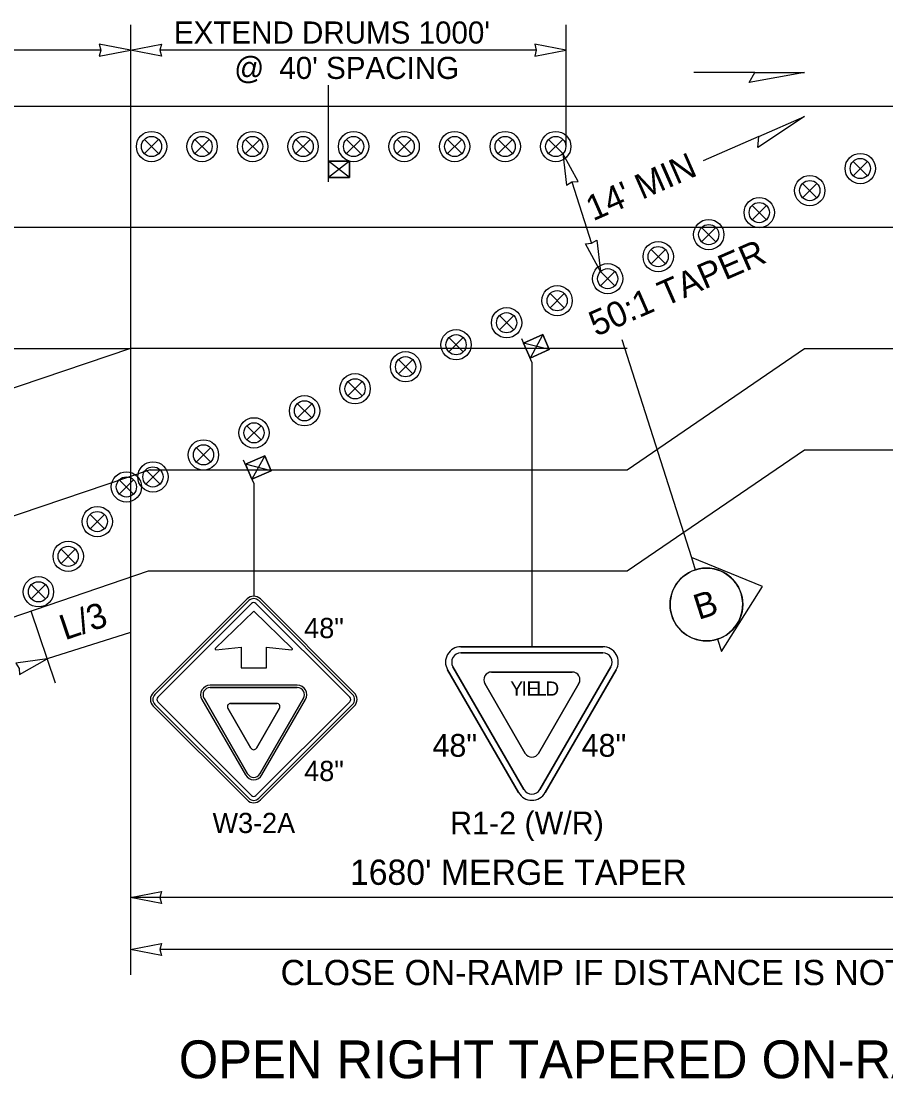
# Model space of a CAD drawing. Extents: x 99999 to 100116, y 99995 to 100013.
# Drawn here: x 100070.257 to 100072.995, y 100004.799 to 100008.148 of the extents above; entities that cross this region are included whole.
import ezdxf

# ---------------------------------------------------------------- set-up
doc = ezdxf.new("R2010")
doc.units = 0
for name, color, linetype in [('RD_MK_LineEdgeYellow', 7, 'Continuous'), ('RD_MK_LineLane', 7, 'Continuous'), ('SH_DE_DetailHeading2Text', 7, 'Continuous'), ('SH_GI_SectionCut', 7, 'Continuous'), ('TR_SN_ConstructionSigns', 7, 'Continuous'), ('TR_WZ_PortableSignMount5ftMinBlk-Org', 7, 'Continuous'), ('TR_WZ_PortableSignMount5ftMinRed-Wht', 7, 'Continuous'), ('TR_WZ_TrafficSafetyDrum', 7, 'Continuous'), ('TR_WZ_WorkZoneDetails', 7, 'Continuous'), ('TR_WZ_WorkZoneTextCurrent', 7, 'Continuous')]:
    doc.layers.add(name, color=color, linetype=linetype)

msp = doc.modelspace()

# ---------------------------------------------------------------- linework, layer by layer
at = {"layer": 'RD_MK_LineEdgeYellow'}
for p, q in [((100068.195, 100007.8789), (100075.43, 100007.8789)), ((100072.1758, 100006.7269), (100072.7368, 100007.1109)), ((100072.7368, 100007.1109), (100075.43, 100007.1109)), ((100070.6655, 100006.7269), (100068.195, 100005.8927)), ((100070.6655, 100006.7269), (100072.1758, 100006.7269))]:
    msp.add_line(p, q, dxfattribs=at)
at = {"layer": 'RD_MK_LineLane'}
for points in [[(100075.43, 100007.4949), (100068.195, 100007.4949)], [(100072.1758, 100007.1109), (100070.6024, 100007.1109)], [(100072.1758, 100007.1109), (100070.6024, 100007.1109)]]:
    msp.add_lwpolyline(points, dxfattribs=at)
at = {"layer": 'SH_GI_SectionCut'}
for p, q in [((100072.1583, 100007.1399), (100072.3791, 100006.4491)), ((100072.3791, 100006.4491), (100072.3915, 100006.4103)), ((100072.6038, 100006.3572), (100072.3791, 100006.4491)), ((100072.474, 100006.1521), (100072.6038, 100006.3572)), ((100072.4616, 100006.1909), (100072.474, 100006.1521))]:
    msp.add_line(p, q, dxfattribs=at)
msp.add_circle((100072.4266, 100006.3006), 0.1152, dxfattribs=at)
for start, end in [(17.7228, 287.7205), (287.7205, 107.725), (287.7205, 17.7228)]:
    msp.add_arc((100072.4266, 100006.3006), 0.1152, start, end, dxfattribs=at)
at = {"layer": 'TR_SN_ConstructionSigns'}
for p, q in [((100070.9719, 100006.3181), (100070.6749, 100006.0211)), ((100071.3113, 100006.0211), (100071.0143, 100006.3181)), ((100070.9772, 100006.3128), (100070.6802, 100006.0158)), ((100070.689, 100006.007), (100070.986, 100006.304)), ((100071.0002, 100006.304), (100071.2971, 100006.007)), ((100071.306, 100006.0158), (100071.009, 100006.3128)), ((100070.9931, 100006.2799), (100070.8713, 100006.1617)), ((100071.1148, 100006.1617), (100070.9931, 100006.2799)), ((100070.8733, 100006.1574), (100070.9531, 100006.1658)), ((100070.9531, 100006.1658), (100070.9531, 100006.0999)), ((100071.0331, 100006.0999), (100071.0331, 100006.1658)), ((100071.0331, 100006.1658), (100071.1128, 100006.1574)), ((100072.0987, 100006.1669), (100071.6491, 100006.1669)), ((100071.6491, 100006.1475), (100071.6491, 100006.1476)), ((100071.6491, 100006.1476), (100071.8739, 100006.1476)), ((100071.8739, 100006.1476), (100071.6491, 100006.1476)), ((100071.6491, 100006.1476), (100071.6491, 100006.1475)), ((100070.9531, 100006.0999), (100071.0331, 100006.0999)), ((100071.8317, 100005.7052), (100071.6069, 100006.0939)), ((100071.6069, 100006.0939), (100071.8317, 100005.7052)), ((100071.8486, 100005.715), (100071.6238, 100006.1036)), ((100071.6238, 100006.1036), (100071.8486, 100005.715)), ((100071.8739, 100006.0867), (100071.7461, 100006.0867)), ((100071.7461, 100006.0867), (100071.8739, 100006.0867)), ((100072.0017, 100006.0867), (100071.8739, 100006.0867)), ((100071.8739, 100006.0867), (100072.0017, 100006.0867)), ((100072.124, 100006.1036), (100071.8992, 100005.715)), ((100071.8992, 100005.715), (100072.124, 100006.1036)), ((100072.1408, 100006.0939), (100071.916, 100005.7052)), ((100071.916, 100005.7052), (100072.1408, 100006.0939)), ((100071.725, 100006.0502), (100071.8528, 100005.8293)), ((100071.8528, 100005.8293), (100071.725, 100006.0502)), ((100071.895, 100005.8293), (100072.0228, 100006.0502)), ((100072.0228, 100006.0502), (100071.895, 100005.8293)), ((100071.1311, 100006.0449), (100070.855, 100006.0449)), ((100070.855, 100006.0374), (100071.1311, 100006.0374)), ((100071.1311, 100006.0374), (100070.855, 100006.0374)), ((100070.6802, 100005.984), (100070.9772, 100005.687)), ((100070.986, 100005.6959), (100070.689, 100005.9929)), ((100070.8291, 100005.9999), (100070.9671, 100005.7608)), ((100070.9736, 100005.7646), (100070.8356, 100006.0037)), ((100070.8356, 100006.0037), (100070.9736, 100005.7646)), ((100071.0662, 100005.9874), (100070.92, 100005.9874)), ((100070.92, 100005.9874), (100071.0662, 100005.9874)), ((100071.2971, 100005.9929), (100071.0002, 100005.6959)), ((100071.009, 100005.687), (100071.306, 100005.984)), ((100071.1506, 100006.0037), (100071.0126, 100005.7646)), ((100071.0126, 100005.7646), (100071.1506, 100006.0037)), ((100071.0191, 100005.7608), (100071.1571, 100005.9999)), ((100070.6749, 100005.9787), (100070.9719, 100005.6817)), ((100070.9113, 100005.9724), (100070.9844, 100005.8458)), ((100070.9844, 100005.8458), (100070.9113, 100005.9724)), ((100071.0017, 100005.8458), (100071.0748, 100005.9724)), ((100071.0748, 100005.9724), (100071.0017, 100005.8458)), ((100071.0143, 100005.6817), (100071.3113, 100005.9787))]:
    msp.add_line(p, q, dxfattribs=at)
for points in [[(100071.6491, 100006.1669), (100072.0987, 100006.1669)], [(100071.8739, 100006.1476), (100072.0987, 100006.1476), (100072.0987, 100006.1475)], [(100072.0987, 100006.1475), (100072.0987, 100006.1476), (100071.8739, 100006.1476)]]:
    msp.add_lwpolyline(points, dxfattribs=at)
for centre, radius, start, end in [((100070.9931, 100006.2969), 0.03, 45, 135), ((100070.9931, 100006.2969), 0.0225, 45, 135), ((100070.9931, 100006.2969), 0.01, 45, 135), ((100070.8731, 100006.1599), 0.0025, 134.1559, 275.9533), ((100071.1131, 100006.1599), 0.0025, 264.0467, 45.8441), ((100071.6491, 100006.1182), 0.0487, 90, 210.0517), ((100071.6491, 100006.1182), 0.0487, 90, 210.0517), ((100072.0987, 100006.1182), 0.0487, 329.9522, 90), ((100072.0987, 100006.1182), 0.0487, 329.9522, 90), ((100071.6491, 100006.1182), 0.0292, 90, 210.0517), ((100071.6491, 100006.1182), 0.0292, 90, 210.0517), ((100072.0987, 100006.1182), 0.0292, 329.9522, 90), ((100072.0987, 100006.1182), 0.0292, 329.9522, 90), ((100071.7461, 100006.0624), 0.0244, 90, 210.0513), ((100071.7461, 100006.0624), 0.0244, 90, 210.0513), ((100072.0017, 100006.0624), 0.0244, 329.9514, 90), ((100072.0017, 100006.0624), 0.0244, 329.9514, 90), ((100070.6961, 100005.9999), 0.03, 135, 225), ((100070.6961, 100005.9999), 0.0225, 135, 225), ((100070.855, 100006.0149), 0.03, 90, 210), ((100070.855, 100006.0149), 0.0225, 90, 210), ((100070.855, 100006.0149), 0.0225, 90, 210), ((100071.1311, 100006.0149), 0.03, 330, 90), ((100071.1311, 100006.0149), 0.0225, 330, 90), ((100071.1311, 100006.0149), 0.0225, 330, 90), ((100071.2901, 100005.9999), 0.0225, 315, 45), ((100071.2901, 100005.9999), 0.03, 315, 45), ((100070.6961, 100005.9999), 0.01, 135, 225), ((100070.92, 100005.9774), 0.01, 90, 210), ((100070.92, 100005.9774), 0.01, 90, 210), ((100071.0662, 100005.9774), 0.01, 330, 90), ((100071.0662, 100005.9774), 0.01, 330, 90), ((100071.2901, 100005.9999), 0.01, 315, 45), ((100070.9931, 100005.8508), 0.01, 210, 330), ((100070.9931, 100005.8508), 0.01, 210, 330), ((100071.8739, 100005.8415), 0.0244, 210.0519, 329.9525), ((100071.8739, 100005.8415), 0.0244, 210.0519, 329.9525), ((100070.9931, 100005.7758), 0.03, 210, 330), ((100070.9931, 100005.7758), 0.0225, 210, 330), ((100070.9931, 100005.7758), 0.0225, 210, 330), ((100071.8739, 100005.7296), 0.0292, 210.0518, 329.9516), ((100071.8739, 100005.7296), 0.0292, 210.0518, 329.9516), ((100070.9931, 100005.7029), 0.03, 225, 315), ((100070.9931, 100005.7029), 0.0225, 225, 315), ((100070.9931, 100005.7029), 0.01, 225, 315), ((100071.8739, 100005.7296), 0.0487, 210.0518, 329.9516), ((100071.8739, 100005.7296), 0.0487, 210.0518, 329.9516)]:
    msp.add_arc(centre, radius, start, end, dxfattribs=at)
at = {"layer": 'TR_WZ_PortableSignMount5ftMinBlk-Org'}
for p, q in [((100071.2294, 100007.6389), (100071.2294, 100007.7189)), ((100071.2961, 100007.7049), (100071.2294, 100007.6529)), ((100071.2961, 100007.6529), (100071.2294, 100007.7049)), ((100071.2627, 100007.6789), (100071.2627, 100007.6789)), ((100071.2628, 100007.679), (100071.2628, 100007.679)), ((100070.9931, 100006.6844), (100070.9611, 100006.7577)), ((100071.0279, 100006.7715), (100070.9875, 100006.6972)), ((100071.0486, 100006.7239), (100070.9667, 100006.7449)), ((100071.0077, 100006.7344), (100071.0077, 100006.7344)), ((100071.0078, 100006.7345), (100071.0078, 100006.7345))]:
    msp.add_line(p, q, dxfattribs=at)
for points in [[(100071.2961, 100007.7049), (100071.2961, 100007.6529), (100071.2294, 100007.6529), (100071.2294, 100007.7049)], [(100071.2294, 100007.6529), (100071.2961, 100007.6529), (100071.2961, 100007.7049), (100071.2294, 100007.7049)], [(100071.0279, 100006.7715), (100071.0486, 100006.7239), (100070.9875, 100006.6972), (100070.9667, 100006.7449)], [(100070.9875, 100006.6972), (100071.0486, 100006.7239), (100071.0279, 100006.7715), (100070.9667, 100006.7449)]]:
    msp.add_lwpolyline(points, close=True, dxfattribs=at)
at = {"layer": 'TR_WZ_PortableSignMount5ftMinRed-Wht'}
for p, q in [((100071.9083, 100007.1554), (100071.868, 100007.0811)), ((100071.8736, 100007.0683), (100071.8416, 100007.1416)), ((100071.9291, 100007.1078), (100071.8472, 100007.1287)), ((100071.8881, 100007.1183), (100071.8881, 100007.1183)), ((100071.8882, 100007.1184), (100071.8882, 100007.1184))]:
    msp.add_line(p, q, dxfattribs=at)
for points in [[(100071.9083, 100007.1554), (100071.9291, 100007.1078), (100071.868, 100007.0811), (100071.8472, 100007.1287)], [(100071.868, 100007.0811), (100071.9291, 100007.1078), (100071.9083, 100007.1554), (100071.8472, 100007.1287)]]:
    msp.add_lwpolyline(points, close=True, dxfattribs=at)
at = {"layer": 'TR_WZ_TrafficSafetyDrum'}
for p, q in [((100070.6468, 100007.7735), (100070.692, 100007.7283)), ((100070.692, 100007.7735), (100070.6468, 100007.7283)), ((100070.8068, 100007.7735), (100070.852, 100007.7283)), ((100070.852, 100007.7735), (100070.8068, 100007.7283)), ((100070.9668, 100007.7735), (100071.012, 100007.7283)), ((100071.012, 100007.7735), (100070.9668, 100007.7283)), ((100071.1268, 100007.7735), (100071.172, 100007.7283)), ((100071.172, 100007.7735), (100071.1268, 100007.7283)), ((100071.2868, 100007.7735), (100071.332, 100007.7283)), ((100071.332, 100007.7735), (100071.2868, 100007.7283)), ((100071.4468, 100007.7735), (100071.492, 100007.7283)), ((100071.492, 100007.7735), (100071.4468, 100007.7283)), ((100071.6068, 100007.7735), (100071.652, 100007.7283)), ((100071.652, 100007.7735), (100071.6068, 100007.7283)), ((100071.7668, 100007.7735), (100071.812, 100007.7283)), ((100071.812, 100007.7735), (100071.7668, 100007.7283)), ((100071.9268, 100007.7735), (100071.972, 100007.7283)), ((100071.972, 100007.7735), (100071.9268, 100007.7283)), ((100072.8913, 100007.7038), (100072.9366, 100007.6585)), ((100072.9366, 100007.7038), (100072.8913, 100007.6585)), ((100072.7313, 100007.634), (100072.7766, 100007.5888)), ((100072.7766, 100007.634), (100072.7313, 100007.5888)), ((100072.5713, 100007.5643), (100072.6166, 100007.519)), ((100072.6166, 100007.5643), (100072.5713, 100007.519)), ((100072.4113, 100007.4946), (100072.4566, 100007.4493)), ((100072.4566, 100007.4946), (100072.4113, 100007.4493)), ((100072.2513, 100007.4248), (100072.2966, 100007.3796)), ((100072.2966, 100007.4248), (100072.2513, 100007.3796)), ((100072.0913, 100007.3551), (100072.1366, 100007.3098)), ((100072.1366, 100007.3551), (100072.0913, 100007.3098)), ((100071.9313, 100007.2853), (100071.9766, 100007.2401)), ((100071.9766, 100007.2853), (100071.9313, 100007.2401)), ((100071.7713, 100007.2156), (100071.8166, 100007.1703)), ((100071.8166, 100007.2156), (100071.7713, 100007.1703)), ((100071.6113, 100007.1458), (100071.6566, 100007.1006)), ((100071.6566, 100007.1458), (100071.6113, 100007.1006)), ((100071.4513, 100007.0761), (100071.4966, 100007.0308)), ((100071.4966, 100007.0761), (100071.4513, 100007.0308)), ((100071.2913, 100007.0063), (100071.3366, 100006.9611)), ((100071.3366, 100007.0063), (100071.2913, 100006.9611)), ((100071.1313, 100006.9366), (100071.1766, 100006.8913)), ((100071.1766, 100006.9366), (100071.1313, 100006.8913)), ((100070.9713, 100006.8669), (100071.0166, 100006.8216)), ((100071.0166, 100006.8669), (100070.9713, 100006.8216)), ((100070.8113, 100006.7971), (100070.8566, 100006.7519)), ((100070.8566, 100006.7971), (100070.8113, 100006.7519)), ((100070.6513, 100006.7274), (100070.6966, 100006.6821)), ((100070.6966, 100006.7274), (100070.6513, 100006.6821)), ((100070.5673, 100006.6956), (100070.6125, 100006.6503)), ((100070.6125, 100006.6956), (100070.5673, 100006.6503)), ((100070.4751, 100006.5857), (100070.5203, 100006.5404)), ((100070.5203, 100006.5857), (100070.4751, 100006.5404)), ((100070.3829, 100006.4758), (100070.4281, 100006.4306)), ((100070.4281, 100006.4758), (100070.3829, 100006.4306)), ((100070.2886, 100006.3636), (100070.3339, 100006.3183)), ((100070.3339, 100006.3636), (100070.2886, 100006.3183))]:
    msp.add_line(p, q, dxfattribs=at)
for centre, radius in [((100070.6694, 100007.7509), 0.048), ((100070.6694, 100007.7509), 0.048), ((100070.8294, 100007.7509), 0.048), ((100070.8294, 100007.7509), 0.048), ((100070.9894, 100007.7509), 0.048), ((100070.9894, 100007.7509), 0.048), ((100071.1494, 100007.7509), 0.048), ((100071.1494, 100007.7509), 0.048), ((100071.3094, 100007.7509), 0.048), ((100071.3094, 100007.7509), 0.048), ((100071.4694, 100007.7509), 0.048), ((100071.4694, 100007.7509), 0.048), ((100071.6294, 100007.7509), 0.048), ((100071.6294, 100007.7509), 0.048), ((100071.7894, 100007.7509), 0.048), ((100071.7894, 100007.7509), 0.048), ((100071.9494, 100007.7509), 0.048), ((100071.9494, 100007.7509), 0.048), ((100070.6694, 100007.7509), 0.032), ((100070.8294, 100007.7509), 0.032), ((100070.9894, 100007.7509), 0.032), ((100071.1494, 100007.7509), 0.032), ((100071.3094, 100007.7509), 0.032), ((100071.4694, 100007.7509), 0.032), ((100071.6294, 100007.7509), 0.032), ((100071.7894, 100007.7509), 0.032), ((100071.9494, 100007.7509), 0.032), ((100072.9139, 100007.6812), 0.048), ((100072.9139, 100007.6812), 0.048), ((100072.9139, 100007.6812), 0.032), ((100072.7539, 100007.6114), 0.048), ((100072.7539, 100007.6114), 0.048), ((100072.7539, 100007.6114), 0.032), ((100072.5939, 100007.5417), 0.048), ((100072.5939, 100007.5417), 0.048), ((100072.5939, 100007.5417), 0.032), ((100072.4339, 100007.4719), 0.048), ((100072.4339, 100007.4719), 0.048), ((100072.4339, 100007.4719), 0.032), ((100072.2739, 100007.4022), 0.048), ((100072.2739, 100007.4022), 0.048), ((100072.2739, 100007.4022), 0.032), ((100072.1139, 100007.3324), 0.048), ((100072.1139, 100007.3324), 0.048), ((100072.1139, 100007.3324), 0.032), ((100071.9539, 100007.2627), 0.048), ((100071.9539, 100007.2627), 0.048), ((100071.9539, 100007.2627), 0.032), ((100071.7939, 100007.1929), 0.048), ((100071.7939, 100007.1929), 0.048), ((100071.7939, 100007.1929), 0.032), ((100071.6339, 100007.1232), 0.048), ((100071.6339, 100007.1232), 0.048), ((100071.6339, 100007.1232), 0.032), ((100071.4739, 100007.0535), 0.048), ((100071.4739, 100007.0535), 0.048), ((100071.4739, 100007.0535), 0.032), ((100071.3139, 100006.9837), 0.048), ((100071.3139, 100006.9837), 0.048), ((100071.3139, 100006.9837), 0.032), ((100071.1539, 100006.914), 0.048), ((100071.1539, 100006.914), 0.048), ((100071.1539, 100006.914), 0.032), ((100070.9939, 100006.8442), 0.048), ((100070.9939, 100006.8442), 0.048), ((100070.9939, 100006.8442), 0.032), ((100070.8339, 100006.7745), 0.048), ((100070.8339, 100006.7745), 0.048), ((100070.8339, 100006.7745), 0.032), ((100070.6739, 100006.7047), 0.048), ((100070.6739, 100006.7047), 0.048), ((100070.5899, 100006.6729), 0.048), ((100070.5899, 100006.6729), 0.048), ((100070.6739, 100006.7047), 0.032), ((100070.5899, 100006.6729), 0.032), ((100070.4977, 100006.5631), 0.048), ((100070.4977, 100006.5631), 0.048), ((100070.4977, 100006.5631), 0.032), ((100070.4055, 100006.4532), 0.048), ((100070.4055, 100006.4532), 0.048), ((100070.4055, 100006.4532), 0.032), ((100070.3113, 100006.3409), 0.048), ((100070.3113, 100006.3409), 0.048), ((100070.3113, 100006.3409), 0.032)]:
    msp.add_circle(centre, radius, dxfattribs=at)
at = {"layer": 'TR_WZ_WorkZoneDetails'}
for p, q in [((100070.6024, 100008.1359), (100070.6024, 100005.1282)), ((100071.9814, 100008.1359), (100071.9814, 100007.7509)), ((100070.5087, 100008.0559), (100068.2887, 100008.0559)), ((100071.8877, 100008.0559), (100070.6962, 100008.0559)), ((100072.5796, 100007.985), (100072.3867, 100007.985)), ((100071.2294, 100007.7136), (100071.2294, 100007.9449)), ((100072.5929, 100007.783), (100072.4163, 100007.7054)), ((100072.0006, 100007.639), (100072.0628, 100007.4443)), ((100069.2533, 100007.1109), (100070.6024, 100007.1109)), ((100070.6024, 100007.1109), (100069.2943, 100006.6692)), ((100071.8736, 100007.0683), (100071.8739, 100006.1669)), ((100072.1758, 100006.4069), (100072.7368, 100006.7909)), ((100072.7368, 100006.7909), (100075.43, 100006.7909)), ((100070.9931, 100006.6844), (100070.9931, 100006.3269)), ((100068.195, 100005.5689), (100070.6601, 100006.4069)), ((100070.6601, 100006.4069), (100072.1758, 100006.4069)), ((100070.6601, 100006.4069), (100072.1758, 100006.4069)), ((100070.2871, 100006.2801), (100070.3643, 100006.0529)), ((100070.6024, 100006.2119), (100070.3386, 100006.1286)), ((100073.1135, 100005.3729), (100070.6024, 100005.3729)), ((100074.3691, 100005.2082), (100070.6962, 100005.2082))]:
    msp.add_line(p, q, dxfattribs=at)
for points in [[(100070.6024, 100008.0559), (100070.5041, 100008.0751), (100070.5087, 100008.0559), (100070.5041, 100008.0366)], [(100070.6024, 100008.0559), (100070.7007, 100008.0751), (100070.6962, 100008.0559), (100070.7007, 100008.0366)], [(100071.9814, 100008.0559), (100071.8831, 100008.0751), (100071.8877, 100008.0559), (100071.8831, 100008.0366)], [(100072.7368, 100007.985), (100072.5618, 100007.9541), (100072.5796, 100007.985)], [(100072.7368, 100007.8463), (100072.589, 100007.7476), (100072.5929, 100007.783)], [(100071.972, 100007.7283), (100071.9836, 100007.6288), (100072.0006, 100007.639), (100072.0203, 100007.6405)], [(100072.0913, 100007.3551), (100072.0433, 100007.443), (100072.063, 100007.4444), (100072.08, 100007.4546)], [(100070.3386, 100006.1286), (100070.2393, 100006.1152), (100070.2498, 100006.0985), (100070.2517, 100006.0787)], [(100070.6024, 100005.3729), (100070.7007, 100005.3922), (100070.6962, 100005.3729), (100070.7007, 100005.3537)], [(100070.6024, 100005.2082), (100070.7007, 100005.2275), (100070.6962, 100005.2082), (100070.7007, 100005.1889)]]:
    msp.add_lwpolyline(points, close=True, dxfattribs=at)

# ---------------------------------------------------------------- texts
at = {"layer": 'SH_DE_DetailHeading2Text'}
msp.add_text('OPEN RIGHT TAPERED ON-RAMP DETAIL', height=0.12, rotation=360, dxfattribs=at).set_placement((100070.7557, 100004.8003))
at = {"layer": 'SH_GI_SectionCut'}
msp.add_text('B', height=0.08, rotation=17.7128, dxfattribs=at).set_placement((100072.4017, 100006.2514))
at = {"layer": 'TR_SN_ConstructionSigns'}
for s, height, p in [('48"', 0.064, (100071.1529, 100006.1942)), ('48"', 0.072, (100072.0316, 100005.8185)), ('48"', 0.064, (100071.1529, 100005.7416)), ('R1-2 (W/R)', 0.072, (100071.6151, 100005.5729)), ('W3-2A', 0.064, (100070.8627, 100005.5769))]:
    msp.add_text(s, height=height, rotation=360, dxfattribs=at).set_placement(p)
for s, height, p in [('Y', 0.045, (100071.8057, 100006.0119)), ('I', 0.045, (100071.8408, 100006.0119)), ('E', 0.045, (100071.857, 100006.0119)), ('L', 0.045, (100071.8876, 100006.0119)), ('D', 0.045, (100071.9168, 100006.0119)), ('48"', 0.072, (100071.5592, 100005.8185))]:
    msp.add_text(s, height=height, dxfattribs=at).set_placement(p)
at = {"layer": 'TR_WZ_WorkZoneTextCurrent'}
for s, height, p in [("EXTEND DRUMS 1000'", 0.07, (100070.7402, 100008.0769)), ('@', 0.07, (100070.9313, 100007.9649)), ("40' SPACING", 0.07, (100071.0741, 100007.9649)), ("1680' MERGE TAPER", 0.08, (100071.2977, 100005.4129)), ('CLOSE ON-RAMP IF DISTANCE IS NOT AVAILABLE', 0.08, (100071.0782, 100005.0953))]:
    msp.add_text(s, height=height, dxfattribs=at).set_placement(p)
for s, rotation, p in [("14' MIN", 23.7238, (100072.0678, 100007.5138)), ('50:1 TAPER', 23.5731, (100072.0771, 100007.1481)), ('L/3', 18.775, (100070.3951, 100006.1869))]:
    msp.add_text(s, height=0.08, rotation=rotation, dxfattribs=at).set_placement(p)

doc.saveas('drawing.dxf')
